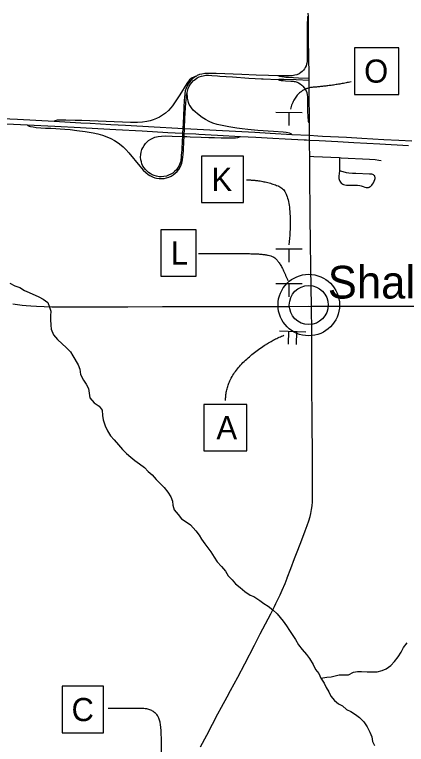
# Model space of a CAD drawing. Extents: x 0 to 34, y 0 to 22.
# Drawn here: x 2.862 to 5.233, y 14.409 to 18.822 of the extents above; entities that cross this region are included whole.
import ezdxf

# ---------------------------------------------------------------- set-up
doc = ezdxf.new("R2010")
doc.units = 0
for name, color, linetype in [('GM_X_Interchange_Ramps', 7, 'Continuous'), ('GM_X_Interstate_Route', 7, 'Continuous'), ('GM_X_Minor_River', 7, 'Continuous'), ('GM_X_State_Route', 7, 'Continuous'), ('GM_X_Township_Road', 7, 'Continuous'), ('GM_X_Unincorporated', 7, 'Continuous'), ('GM_X_Unincorporated_Location', 7, 'Continuous'), ('GM_X_Unincorporated_Text', 7, 'Continuous'), ('SH_Text', 7, 'Continuous'), ('SN_P_Signs', 7, 'Continuous')]:
    doc.layers.add(name, color=color, linetype=linetype)

msp = doc.modelspace()

# ---------------------------------------------------------------- linework, layer by layer
at = {"layer": 'GM_X_Interchange_Ramps'}
msp.add_line((4.3656, 18.4336), (4.4562, 18.4297), dxfattribs=at)
for points in [[(4.6393, 18.8136), (4.6377, 18.8127), (4.6365, 18.8117), (4.6348, 18.8082), (4.6343, 18.8052), (4.6334, 18.7926), (4.6324, 18.773), (4.6316, 18.711), (4.6324, 18.6639), (4.633, 18.5851), (4.6332, 18.5606), (4.6327, 18.5451), (4.6323, 18.538), (4.6308, 18.5294), (4.6291, 18.5227), (4.6258, 18.513), (4.6205, 18.5019), (4.6159, 18.4943), (4.6101, 18.4866), (4.6024, 18.4786), (4.5942, 18.4722), (4.5834, 18.4651), (4.5703, 18.4591), (4.5585, 18.4552), (4.5492, 18.4537), (4.5406, 18.4528), (4.5247, 18.4528), (4.5101, 18.4528), (4.4898, 18.4522), (4.4745, 18.4521), (4.4571, 18.4514)], [(3.9635, 18.451), (3.9555, 18.4482), (3.9457, 18.4447), (3.9366, 18.4405), (3.9286, 18.4345), (3.9209, 18.4277), (3.9141, 18.4198), (3.9043, 18.4059), (3.861, 18.3377), (3.8411, 18.3062), (3.8176, 18.2714), (3.8073, 18.2578), (3.7928, 18.2417), (3.7755, 18.2262), (3.758, 18.2133), (3.7394, 18.2021), (3.7213, 18.1932), (3.7011, 18.1853), (3.6832, 18.1798), (3.662, 18.1751), (3.6358, 18.1717), (3.6064, 18.1703), (3.5644, 18.1706), (3.2691, 18.1813), (3.2296, 18.1823), (3.1723, 18.1838), (3.1506, 18.1843), (3.1345, 18.1845), (3.126, 18.184), (3.1206, 18.1832), (3.1132, 18.1815), (3.1079, 18.1799), (3.1016, 18.1775)], [(3.9635, 18.451), (3.9515, 18.4433), (3.9387, 18.4336), (3.928, 18.4235), (3.9196, 18.4134), (3.9122, 18.403), (3.9054, 18.3902), (3.8994, 18.3771), (3.8947, 18.361), (3.8916, 18.3428), (3.8896, 18.322), (3.8885, 18.3042), (3.886, 18.2601), (3.8812, 18.1643), (3.8797, 18.1343), (3.8782, 18.1048), (3.8772, 18.0851), (3.876, 18.0604), (3.873, 18.0056), (3.8709, 17.972), (3.8699, 17.9579), (3.8686, 17.9445), (3.8669, 17.9357), (3.8642, 17.926), (3.8608, 17.9156), (3.8558, 17.9055), (3.8484, 17.894), (3.8413, 17.8846), (3.8299, 17.8729), (3.8188, 17.8645), (3.807, 17.8567), (3.7942, 17.8507), (3.7804, 17.846), (3.7653, 17.8426), (3.7498, 17.8413), (3.7367, 17.842), (3.7209, 17.8447), (3.7075, 17.8484), (3.6944, 17.8538), (3.6826, 17.8605), (3.6729, 17.8669), (3.6634, 17.875), (3.6537, 17.8851), (3.6456, 17.8951), (3.6389, 17.9063), (3.6329, 17.92), (3.6292, 17.9328), (3.6262, 17.9449), (3.6248, 17.9604), (3.6262, 17.977), (3.6286, 17.9908), (3.6329, 18.0058), (3.6378, 18.0172), (3.6454, 18.0307), (3.6537, 18.042), (3.6622, 18.0511), (3.6727, 18.0603), (3.6856, 18.0689), (3.6938, 18.0732), (3.7112, 18.0802), (3.7308, 18.085), (3.7509, 18.0875), (3.7742, 18.0884), (3.8159, 18.0871), (3.8762, 18.0852)], [(3.9055, 18.3503), (3.9132, 18.3748), (3.9192, 18.3888), (3.926, 18.4008), (3.934, 18.4119), (3.9444, 18.4231), (3.9537, 18.4309), (3.9665, 18.4392), (3.9788, 18.4453), (3.9929, 18.4502), (4.0034, 18.453), (4.0184, 18.4553), (4.0351, 18.4556), (4.0553, 18.4539), (4.0898, 18.4517)], [(4.0795, 18.4662), (4.0309, 18.4672), (4.014, 18.4662), (3.9959, 18.4631), (3.9811, 18.4595), (3.9673, 18.4534), (3.9635, 18.451)], [(4.4571, 18.4514), (4.3986, 18.4535), (4.324, 18.4562), (4.2366, 18.4593), (4.082, 18.4661), (4.0795, 18.4662)], [(4.0898, 18.4517), (4.1047, 18.4507), (4.1801, 18.4458), (4.2791, 18.4389), (4.3555, 18.4341), (4.3656, 18.4336)], [(4.644, 18.4368), (4.5795, 18.4386), (4.5191, 18.4415), (4.5038, 18.4425), (4.4935, 18.4436), (4.4791, 18.4458), (4.4665, 18.4484), (4.4571, 18.4514)], [(4.4562, 18.4297), (4.4622, 18.4313), (4.4689, 18.432), (4.4789, 18.4324), (4.4909, 18.4322), (4.5657, 18.4291), (4.6441, 18.426)], [(4.4562, 18.4297), (4.4657, 18.4266), (4.4752, 18.4244), (4.4865, 18.4232), (4.5005, 18.4223), (4.5333, 18.4202), (4.5477, 18.4191), (4.5543, 18.4184), (4.5605, 18.4171), (4.566, 18.4155), (4.5724, 18.4132), (4.5792, 18.4102), (4.59, 18.404), (4.5998, 18.3963), (4.607, 18.3893), (4.6149, 18.3799), (4.6205, 18.3717), (4.626, 18.3617), (4.6301, 18.3512), (4.6329, 18.3377), (4.6342, 18.325), (4.6348, 18.3104), (4.635, 18.2599), (4.6352, 18.2411), (4.6358, 18.2045), (4.6378, 18.1818), (4.6388, 18.1774), (4.6411, 18.1729), (4.6432, 18.1709), (4.6457, 18.1692)], [(2.9376, 18.156), (2.9429, 18.1519), (2.9503, 18.1482), (2.9586, 18.1457), (2.9753, 18.1428), (2.9931, 18.1403), (3.0208, 18.1384), (3.0487, 18.1366), (3.0814, 18.1352), (3.1108, 18.1335), (3.1388, 18.1318), (3.1666, 18.1294), (3.1976, 18.1271), (3.2393, 18.1225), (3.2901, 18.1153), (3.3376, 18.1071), (3.3665, 18.1008), (3.395, 18.0931), (3.4212, 18.0833), (3.4452, 18.0724), (3.4657, 18.0612), (3.488, 18.047), (3.5079, 18.0321), (3.5184, 18.023), (3.5352, 18.0068), (3.554, 17.9861), (3.6189, 17.9066), (3.6405, 17.8821), (3.656, 17.8668), (3.6706, 17.855), (3.6795, 17.849), (3.6961, 17.8404), (3.7107, 17.8351), (3.7212, 17.8325), (3.7366, 17.8307), (3.7506, 17.8306), (3.7661, 17.8321), (3.7813, 17.8354), (3.7961, 17.8403), (3.8088, 17.8461), (3.8222, 17.854), (3.8344, 17.8636), (3.8455, 17.8744), (3.8554, 17.8865), (3.8636, 17.8997), (3.8702, 17.9137), (3.874, 17.9239), (3.8789, 17.9451), (3.882, 17.976), (3.8836, 18.0024), (3.8861, 18.0552), (3.8876, 18.0848), (3.8885, 18.1042), (3.8894, 18.1205), (3.89, 18.1337), (3.8931, 18.1965), (3.8982, 18.2897), (3.9014, 18.322), (3.9031, 18.3359), (3.9055, 18.3503)], [(4.5398, 18.0983), (4.5346, 18.1009), (4.5262, 18.1051), (4.5151, 18.1083), (4.5052, 18.11), (4.4862, 18.1119), (4.4289, 18.1159), (4.3329, 18.1218), (4.2725, 18.127), (4.2386, 18.1307), (4.2063, 18.1353), (4.1573, 18.1432), (4.1176, 18.1508), (4.0874, 18.1582), (4.0624, 18.1663), (4.0395, 18.1761), (4.0175, 18.1876), (3.9965, 18.2008), (3.9691, 18.2213), (3.9551, 18.2335), (3.9427, 18.2452), (3.9315, 18.258), (3.9238, 18.2697), (3.9182, 18.2795), (3.9141, 18.2908), (3.9115, 18.3001), (3.9086, 18.3171), (3.9055, 18.3503)], [(3.8788, 18.0851), (3.8876, 18.0848), (3.9036, 18.0843), (3.9251, 18.0836), (3.9903, 18.0812), (4.0374, 18.0799), (4.071, 18.079), (4.1127, 18.0777), (4.1235, 18.0774), (4.1631, 18.0764), (4.183, 18.0764), (4.1981, 18.0774), (4.2119, 18.0791), (4.2196, 18.0818), (4.2297, 18.0862)]]:
    msp.add_lwpolyline(points, dxfattribs=at)
at = {"layer": 'GM_X_Interstate_Route'}
for points in [[(1.6712, 18.2556), (1.6811, 18.255), (1.8299, 18.2468), (1.9895, 18.238), (2.0871, 18.2327), (2.1179, 18.231), (2.2494, 18.2237), (2.3748, 18.2168), (2.6198, 18.2033), (2.7362, 18.1969), (2.8807, 18.1892), (3.1016, 18.1775)], [(1.6712, 18.2285), (1.8262, 18.2205), (1.9127, 18.216), (2.0775, 18.2064), (2.1339, 18.2032), (2.2859, 18.1944), (2.4043, 18.1875), (2.5443, 18.1793), (2.6654, 18.1723), (2.8146, 18.1625), (2.9376, 18.156), (3.1048, 18.1479), (3.2602, 18.1391), (3.3648, 18.1332), (3.4756, 18.1269), (3.633, 18.1185), (3.7896, 18.1094), (3.8782, 18.1048), (3.8885, 18.1042), (3.9578, 18.1006)], [(3.1016, 18.1775), (3.1667, 18.1738), (3.2639, 18.1683), (3.3188, 18.1653), (3.4454, 18.1584), (3.5325, 18.1539), (3.706, 18.144), (3.8504, 18.1359), (3.8797, 18.1343), (3.89, 18.1337), (4.0816, 18.1235), (4.3153, 18.1108), (4.4084, 18.1056), (4.5398, 18.0983), (4.6464, 18.0924), (4.6958, 18.0896), (4.7248, 18.0881), (4.8697, 18.0804), (4.963, 18.0755), (5.0966, 18.0681), (5.1865, 18.0631), (5.2649, 18.0588)], [(3.9578, 18.1006), (3.9776, 18.0995), (4.0895, 18.0936), (4.2297, 18.0862), (4.3215, 18.0809), (4.424, 18.0751), (4.4993, 18.0712), (4.6133, 18.0654), (4.6287, 18.0647)], [(4.6287, 18.0647), (4.6466, 18.0638), (4.7054, 18.061), (4.8174, 18.0549), (4.9148, 18.0495), (4.9939, 18.0451), (5.0725, 18.0406), (5.2443, 18.0308)]]:
    msp.add_lwpolyline(points, dxfattribs=at)
at = {"layer": 'GM_X_Minor_River'}
for points in [[(2.8339, 17.1989), (2.8643, 17.1832), (2.8948, 17.1712), (2.9224, 17.1535), (2.95, 17.1414), (3.009, 17.1155), (3.0357, 17.1007), (3.0633, 17.082), (3.0741, 17.0536), (3.0819, 17.029), (3.0803, 17.0015), (3.0797, 16.9777), (3.0819, 16.9436), (3.0841, 16.9199), (3.0968, 16.8859), (3.1208, 16.8567), (3.1504, 16.8314), (3.1743, 16.8089), (3.2011, 16.7826), (3.2147, 16.7581), (3.2474, 16.7053), (3.2563, 16.6779), (3.2614, 16.6457), (3.2797, 16.6117), (3.2961, 16.5872), (3.3096, 16.5608), (3.3128, 16.5323), (3.3178, 16.5049), (3.3437, 16.4748), (3.3733, 16.4552), (3.3925, 16.4307), (3.3938, 16.3985), (3.3979, 16.3729), (3.4097, 16.335), (3.4242, 16.3048), (3.4425, 16.2756), (3.4646, 16.2512), (3.4914, 16.2202), (3.5154, 16.192), (3.5394, 16.1685), (3.5652, 16.147), (3.5891, 16.1264), (3.6186, 16.1058), (3.6473, 16.0834), (3.6712, 16.059), (3.6951, 16.0384), (3.7182, 16.0111), (3.7431, 15.9876), (3.767, 15.9632), (3.7891, 15.9341), (3.8083, 15.9058), (3.8181, 15.8793), (3.8203, 15.8556), (3.8281, 15.8282), (3.8512, 15.799), (3.8723, 15.7727), (3.9, 15.7559), (3.9267, 15.7363), (3.9593, 15.7016), (3.9785, 15.6742), (3.9939, 15.6497), (4.0132, 15.6224), (4.0314, 15.598), (4.0488, 15.5735), (4.0699, 15.5405), (4.0882, 15.5132), (4.1141, 15.484), (4.1372, 15.4577), (4.1536, 15.4294), (4.1775, 15.4041), (4.1977, 15.3796), (4.2273, 15.3572), (4.255, 15.3338), (4.2865, 15.3123), (4.3102, 15.3031)], [(4.3102, 15.3031), (4.3455, 15.2798), (4.3694, 15.262), (4.3961, 15.2443), (4.4248, 15.2228), (4.4506, 15.1984), (4.4861, 15.1551), (4.5073, 15.126), (4.5256, 15.0977), (4.5419, 15.0732), (4.5612, 15.044), (4.5796, 15.011), (4.6026, 14.9837), (4.6275, 14.9536), (4.6468, 14.9282), (4.6689, 14.8924), (4.6835, 14.8631), (4.7036, 14.8377), (4.7144, 14.8103), (4.7346, 14.7802), (4.7462, 14.7528), (4.7626, 14.7273), (4.7762, 14.7), (4.7982, 14.6746), (4.8221, 14.654), (4.8459, 14.6419), (4.8708, 14.6204), (4.8956, 14.6074), (4.9242, 14.5897), (4.948, 14.5719), (4.9749, 14.5447), (4.996, 14.5155), (5.0106, 14.4834), (5.0241, 14.4551), (5.0273, 14.4276), (5.0399, 14.4021)], [(4.7144, 14.8103), (4.7522, 14.8165), (4.7768, 14.8186), (4.8023, 14.8246), (4.8268, 14.8297), (4.8543, 14.829), (4.8827, 14.8294), (4.9118, 14.8468), (4.9364, 14.8509), (4.961, 14.8502), (4.9961, 14.8487), (5.0255, 14.8472), (5.0558, 14.8475), (5.085, 14.8555), (5.1095, 14.8662), (5.1387, 14.8855), (5.1602, 14.9105), (5.1835, 14.9383), (5.2002, 14.9669), (5.216, 14.9956), (5.2375, 15.0224)]]:
    msp.add_lwpolyline(points, dxfattribs=at)
at = {"layer": 'GM_X_State_Route'}
for points in [[(4.6469, 18.031), (4.6466, 18.0638), (4.6464, 18.0924), (4.6457, 18.1692), (4.6456, 18.1825), (4.6447, 18.3425), (4.6441, 18.426), (4.644, 18.4368), (4.6439, 18.4575), (4.641, 18.671), (4.6393, 18.8136), (4.6391, 18.8312)], [(4.6577, 17.0584), (4.6538, 17.2907), (4.6524, 17.4477), (4.651, 17.5952), (4.6486, 17.8732), (4.6474, 17.9655), (4.6469, 18.031)], [(2.8522, 17.0732), (2.8795, 17.0687), (2.9072, 17.0649), (2.9319, 17.0627), (2.9614, 17.0604), (2.9939, 17.0584), (3.0867, 17.0559), (3.2979, 17.0554), (3.5479, 17.0561), (3.7573, 17.0567)], [(3.7573, 17.0567), (3.8893, 17.057), (4.0213, 17.0572), (4.1719, 17.0564), (4.5274, 17.0566), (4.6577, 17.0584)], [(4.5111, 15.4136), (4.512, 15.4159), (4.5335, 15.4725), (4.5563, 15.5335), (4.5749, 15.5829), (4.5993, 15.6468), (4.6199, 15.7004), (4.6327, 15.7337), (4.6422, 15.7616), (4.6497, 15.7868), (4.6545, 15.8063), (4.6588, 15.8306), (4.6616, 15.8521), (4.6635, 15.8767), (4.6646, 15.9108), (4.6636, 16.1555), (4.6632, 16.3635), (4.6614, 16.6011), (4.6608, 16.7066), (4.6601, 16.8224), (4.6599, 16.8982), (4.6577, 17.0584)], [(4.6577, 17.0584), (4.6719, 17.0586), (4.8165, 17.0591), (4.9422, 17.0592), (5.0742, 17.0593), (5.1907, 17.0592), (5.332, 17.0595), (5.4299, 17.0596), (5.6552, 17.0603), (5.7656, 17.0598), (5.8976, 17.0605), (6.0606, 17.061), (6.1943, 17.0607), (6.2875, 17.0608), (6.3916, 17.0608), (6.5361, 17.0621), (6.7302, 17.0625), (6.7877, 17.0628), (6.8854, 17.0627), (7.2296, 17.0624), (7.2744, 17.0624), (7.2979, 17.0623), (7.5027, 17.0624), (7.7699, 17.0625)], [(4.3484, 15.0775), (4.4114, 15.1992), (4.4339, 15.2436), (4.4427, 15.2608), (4.468, 15.313), (4.4811, 15.3414), (4.4982, 15.3813), (4.5111, 15.4136)], [(3.9874, 14.394), (4.0249, 14.4655), (4.0597, 14.5315), (4.0926, 14.5932), (4.1144, 14.6343), (4.148, 14.6973), (4.1686, 14.7356), (4.2119, 14.8163), (4.2546, 14.8973), (4.3128, 15.0088), (4.3484, 15.0775)]]:
    msp.add_lwpolyline(points, dxfattribs=at)
at = {"layer": 'GM_X_Township_Road'}
for points in [[(4.6474, 17.9655), (4.6727, 17.9644), (4.8285, 17.9576), (4.8389, 17.9572), (5.0095, 17.9481), (5.0435, 17.9458), (5.0666, 17.943), (5.0789, 17.9411)], [(4.8285, 17.9576), (4.8282, 17.9434), (4.827, 17.8984), (4.8273, 17.8782), (4.8234, 17.8445), (4.8239, 17.8321), (4.8249, 17.8259), (4.827, 17.8201), (4.8301, 17.8147), (4.8387, 17.8037), (4.8421, 17.8005), (4.8473, 17.7972), (4.853, 17.7948), (4.8606, 17.7929), (4.8698, 17.7917), (4.8838, 17.7913), (4.9195, 17.7913), (4.9366, 17.7907), (4.9505, 17.7894), (4.9581, 17.7877), (4.9711, 17.7825), (4.9813, 17.7786), (4.9888, 17.7767), (4.9965, 17.7765), (5.0026, 17.7777), (5.007, 17.7792), (5.0125, 17.782), (5.0176, 17.7856), (5.0232, 17.791), (5.0281, 17.797), (5.0331, 17.8049), (5.0381, 17.8146), (5.0422, 17.8247), (5.0438, 17.8307), (5.0441, 17.8354), (5.0417, 17.8453), (5.041, 17.8467), (5.0381, 17.8503), (5.0344, 17.8532), (5.0302, 17.8552), (5.0242, 17.8567), (5.0165, 17.8574), (5.0087, 17.8577), (4.9259, 17.861), (4.9071, 17.8621), (4.8834, 17.8643), (4.8705, 17.8661), (4.8501, 17.8717), (4.8273, 17.8782)]]:
    msp.add_lwpolyline(points, dxfattribs=at)
at = {"layer": 'GM_X_Unincorporated'}
for radius in [0.186, 0.1179]:
    msp.add_circle((4.6419, 17.0659), radius, dxfattribs=at)
at = {"layer": 'GM_X_Unincorporated_Location'}
msp.add_line((4.6419, 17.0659), (4.6419, 17.0659), dxfattribs=at)
at = {"layer": 'SH_Text'}
for points in [[(4.9191, 18.3387), (5.1866, 18.3387), (5.1866, 18.6223), (4.9191, 18.6223)], [(3.992, 17.6857), (4.2471, 17.6857), (4.2471, 17.9663), (3.992, 17.9663)], [(3.747, 17.2404), (3.9604, 17.2404), (3.9604, 17.5204), (3.747, 17.5204)], [(4.0076, 16.1841), (4.2679, 16.1841), (4.2679, 16.4648), (4.0076, 16.4648)], [(3.1492, 14.4783), (3.4001, 14.4783), (3.4001, 14.761), (3.1492, 14.761)]]:
    msp.add_lwpolyline(points, close=True, dxfattribs=at)
for points in [[(4.8985, 18.4156), (4.779, 18.3909), (4.5646, 18.3757), (4.5305, 18.2504)], [(4.2642, 17.8229), (4.3671, 17.8229), (4.553, 17.7465), (4.5217, 17.43)], [(3.9742, 17.3769), (4.1455, 17.3769), (4.3905, 17.3769), (4.4668, 17.3355), (4.5148, 17.215)], [(4.1384, 16.4878), (4.1384, 16.6184), (4.3669, 16.8342), (4.4916, 16.883)], [(3.4273, 14.6286), (3.526, 14.6286), (3.7233, 14.6286), (3.7574, 14.4615), (3.7391, 14.1553)]]:
    msp.add_open_spline(points, degree=2, dxfattribs=at)
at = {"layer": 'SN_P_Signs'}
for p, q in [((4.4423, 18.2317), (4.6023, 18.2306)), ((4.5223, 18.2311), (4.5217, 18.1511)), ((4.4423, 17.4063), (4.6023, 17.4051)), ((4.5223, 17.4057), (4.5217, 17.3257)), ((4.4423, 17.1969), (4.6023, 17.1958)), ((4.5223, 17.1963), (4.5217, 17.1164)), ((4.4641, 16.9107), (4.624, 16.9042)), ((4.52, 16.9084), (4.5168, 16.8285)), ((4.544, 16.9074), (4.544, 16.9074)), ((4.544, 16.9074), (4.544, 16.9074)), ((4.568, 16.9065), (4.5648, 16.8265))]:
    msp.add_line(p, q, dxfattribs=at)

# ---------------------------------------------------------------- texts
at = {"layer": 'GM_X_Unincorporated_Text'}
msp.add_text('Shalersville', height=0.197443, rotation=0, dxfattribs=at).set_placement((4.7567, 17.1057))
at = {"layer": 'SH_Text'}
for s, p in [('O', (4.9769, 18.4108)), ('K', (4.0532, 17.7563)), ('L', (3.8076, 17.3104)), ('A', (4.0834, 16.2548)), ('C', (3.2068, 14.55))]:
    msp.add_text(s, height=0.14, dxfattribs=at).set_placement(p)

doc.saveas('drawing.dxf')
